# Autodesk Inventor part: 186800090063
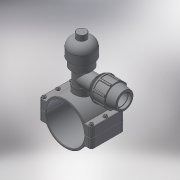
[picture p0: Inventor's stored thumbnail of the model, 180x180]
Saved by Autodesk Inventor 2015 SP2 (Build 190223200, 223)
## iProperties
Created: 2017-05
Part Number: 186800090063
Material: Generic
Description: PLASSON MECHANICAL TAPPING VALVE 90-63
Document SubType Name: Modeling
Designer: KIM
Density: 1 g/cm^3
Appearance: Default
Author: KIM
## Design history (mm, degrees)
derived "18680.ipt"
feature "Solid1::18680.ipt"
feature "Solid2::18680.ipt"
tag "TaggingFeature1"
body "Solid1"
other parameters: "d0" = 99, "d1" = 141, "d2" = 45, "d4" = 105, "d5" = 0, "d6" = 7.05, "d7" = 141, "d8" = 0.1, "d10" = 0, "d11" = 0.9, "d14" = 73.6528, "d20" = 0.9, "d23" = 0.9, "d36" = 13, "d37" = 10.4, "d38" = 53, "d39" = 0, "d40" = 3, "d41" = 5, "d42" = 0, "d43" = 8, "d44" = 3, "d45" = 0, "d46" = 0.9, "d51" = 75, "d52" = 56.656, "d53" = 21, "d54" = 0, "d57" = 0, "d58" = 97.2, "d60" = 0, "d62" = 13, "d63" = 10.4, "d66" = 84.2, "d67" = 63, "d68" = 16.66667, "d70" = 113, "d71" = 84.75, "d72" = 2.85714, "d73" = 90.4, "d74" = 120 deg, "d75" = 81.9, "d76" = 10 deg, "d77" = 101.7, "d80" = 50.4, "d82" = 11, "d87" = 28.57143, "d90" = 105.09, "d91" = 35 deg, "d92" = 17.5 deg, "d94" = 0, "d96" = 360 deg, "d98" = 1.26, "d99" = 121, "d100" = 67.8, "d101" = 135 deg, "d102" = 2.26, "d105" = 5.65, "d106" = 0, "d107" = 0.1, "d109" = 73.6528, "d112" = 34.85714, "d113" = 6.66667, "d116" = 0, "d121" = 67.9872, "d122" = 113.312, "d123" = 96.3152, "d124" = 45 deg, "d125" = 219.6, "d126" = 244, "d127" = 146.4, "d128" = 1, "d129" = 65, "G_" = 56.656, "A_" = 75, "L_" = 141, "L_1" = 105, "l_2" = 21, "d_1" = 63, "E_" = 113, "H_1" = 65, "H_2" = 244
